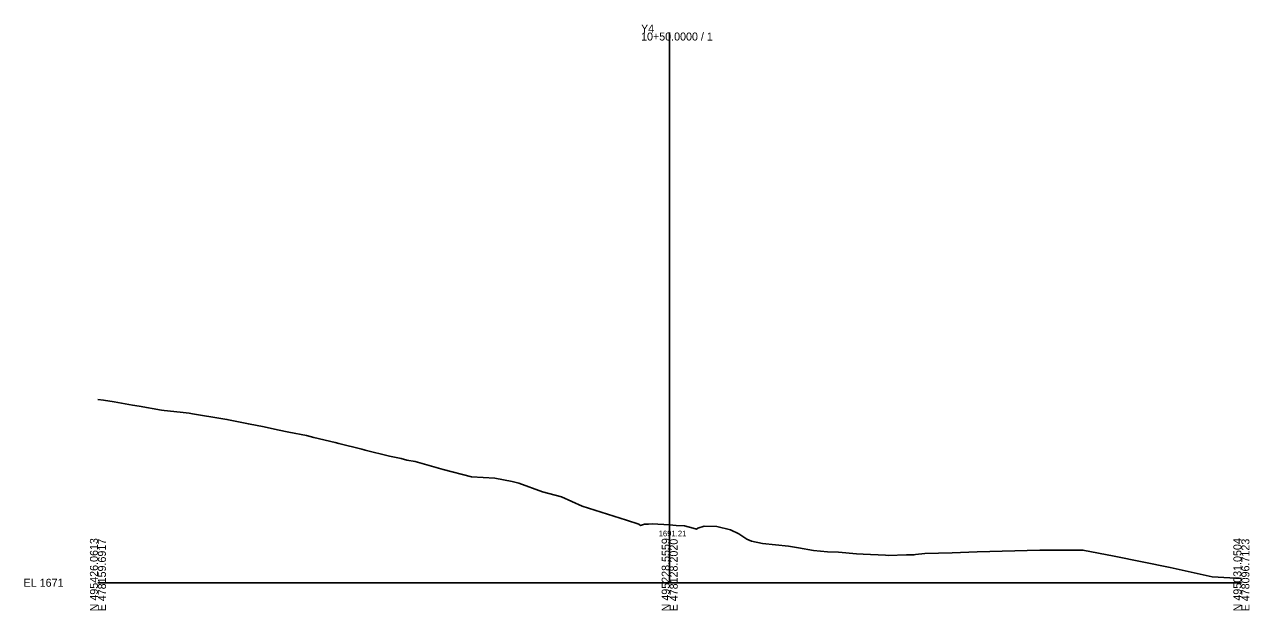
# Model space of a CAD drawing. Extents: x -26 to 403, y -10 to 5108.
# Drawn here: x -25.7 to 402.8, y 490.3 to 695.2 of the extents above; entities that cross this region are included whole.
import ezdxf

# ---------------------------------------------------------------- set-up
doc = ezdxf.new("R2010")
doc.units = 0
for name, color, linetype in [('Exist Cross Section Cell', 7, 'Continuous'), ('Exist XS Center Line Elevation Label', 7, 'Continuous'), ('Exist XS Ground Line', 7, 'Continuous')]:
    doc.layers.add(name, color=color, linetype=linetype)

msp = doc.modelspace()

# ---------------------------------------------------------------- linework, layer by layer
at = {"layer": 'Exist Cross Section Cell'}
for p, q in [((200, 500), (200, 692.4)), ((0, 500), (200, 500)), ((200, 500), (400, 500))]:
    msp.add_line(p, q, dxfattribs=at)
at = {"layer": 'Exist XS Ground Line'}
msp.add_lwpolyline([(0, 564.13), (2, 563.81), (5.68, 563.23), (12.13, 562.08), (14.41, 561.72), (22.26, 560.4), (23.15, 560.27), (28.76, 559.63), (31.88, 559.31), (33.07, 559.1), (43.7, 557.32), (45.12, 557.1), (52.64, 555.56), (58.09, 554.51), (62.77, 553.49), (66.83, 552.65), (72.9, 551.45), (75.56, 550.85), (83.02, 549.02), (84.3, 548.71), (92.28, 546.69), (93.15, 546.48), (93.49, 546.39), (102.04, 544.3), (106.1, 543.43), (108.05, 542.91), (110.97, 542.37), (120.78, 539.66), (130.69, 537.05), (138.89, 536.53), (144.89, 535.4), (147.2, 534.8), (155.56, 531.84), (162.15, 530.04), (169.44, 526.79), (184.9, 521.89), (189.23, 520.47), (189.74, 520.06), (191.2, 520.45), (192.62, 520.47), (193.9, 520.63), (200, 520.21), (202.3, 520.05), (205.22, 519.87), (208.21, 519.06), (209.41, 518.74), (209.85, 519.14), (212.05, 519.83), (216.47, 519.64), (221.33, 518.54), (224.2, 517.12), (226.97, 515.22), (228.64, 514.55), (232.44, 513.76), (241.54, 512.74), (245.08, 512.17), (250.27, 511.34), (255.21, 510.84), (259.01, 510.65), (265.33, 510.17), (267.74, 509.98), (275.46, 509.64), (276.48, 509.59), (282.86, 509.75), (285.21, 509.81), (285.59, 509.82), (285.95, 509.85), (289.22, 510.21), (298.85, 510.47), (307.54, 510.87), (329.54, 511.39), (344.59, 511.4), (355.53, 509.26), (375.08, 505.38), (389.83, 502.09), (400, 501.45)], dxfattribs=at)

# ---------------------------------------------------------------- texts
at = {"layer": 'Exist Cross Section Cell'}
for s, p in [('Y4', (190, 692.4)), ('10+50.0000 / 1', (190, 689.6)), ('EL 1671', (-26, 498.6))]:
    msp.add_text(s, height=2.8, dxfattribs=at).set_placement(p)
for s, p in [('N 495426.0613', (0, 490)), ('E 478159.6917', (2.8, 490)), ('N 495228.5559', (200, 490)), ('E 478128.2020', (202.8, 490)), ('N 495031.0504', (400, 490)), ('E 478096.7123', (402.8, 490))]:
    msp.add_text(s, height=2.8, rotation=90, dxfattribs=at).set_placement(p)
at = {"layer": 'Exist XS Center Line Elevation Label'}
msp.add_text('1691.21', height=2, dxfattribs=at).set_placement((196.17, 516.21))

doc.saveas('drawing.dxf')
